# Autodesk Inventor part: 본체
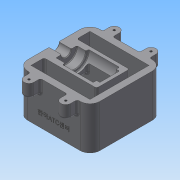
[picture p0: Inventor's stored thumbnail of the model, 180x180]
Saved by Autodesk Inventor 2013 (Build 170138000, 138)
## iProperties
Created: 2018-01
Part Number: 본체
Material: 일반
Document SubType Name: Modeling
Designer: Administrator
Density: 1 g/cm^3
Mass: 367.227 g
Surface Area: 841.146 cm^2
Volume: 367.227 cm^3
Author: Administrator
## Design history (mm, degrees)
sketch "스케치1"
  geometry: L1 (-55, -55)-(55, -55); L2 (55, -55)-(55, 55); L3 (55, 55)-(-55, 55); L4 (-55, 55)-(-55, -55); L5 (-55, -55)-(55, 55); L6 (55, -55)-(-55, 55); 1 further point
  constraints: 12 end point, 2 midpoint, 2 parallel, 1 horizontal, 1 perpendicular
  dimensions: "d0" = 110 distance of L3.end L2.end; "d1" = 110 distance of L2.end L1.end
extrude "돌출1" new body sketch "스케치1" distance "d2" = 65; taper "d3" = 0 deg
sketch "스케치2"
  geometry: L1 (55, 55)-(-55, 55) reference; L2 (-55, 55)-(-55, -55) reference; L3 (-55, -55)-(55, -55) reference; L4 (55, -55)-(55, 55) reference; L5 (55, 55)-(-55, 55) reference; L6 (-55, 55)-(-55, -55) reference; L7 (-55, 65)-(-1, 65); L8 (0, 55)-(0, 82.345); L9 (-35.5, 65)-(-35.5, 55); L10 (-20.5, 65)-(-20.5, 55); L11 (-35.5, 55)-(-20.5, 55); L12 (20.5, 65)-(20.5, 55); L13 (35.5, 55)-(20.5, 55); L14 (35.5, 65)-(35.5, 55); A1 r 7.5 centre (-28, 65) between (-20.5, 65) and (-35.5, 65); A2 r 7.5 centre (28, 65) between (35.5, 65) and (20.5, 65); 3 further points
  constraints: 16 end point, 5 symmetric about line, 4 midpoint, 4 point on circle, 4 point on line, 3 perpendicular, 2 centre point, 2 tangent, 1 coincident, 1 collinear, 1 horizontal alignment, 1 parallel, 1 other
  dimensions: "d5" = 7.5 radius of A1; "d6" = 27 distance from line of L2 A1.centre; "d7" = 10 distance from line of L1 A2.centre
extrude "돌출2" join sketch "스케치2" distance "d8" = 20; taper "d9" = 0 deg
sketch "스케치3"
  geometry: A1 r 7.5 centre (-28, -65) between (-35.5, -65) and (-20.5, -65) reference; A2 r 7.5 centre (28, -65) between (20.5, -65) and (35.5, -65) reference; A3 r 7.5 centre (28, 65) between (35.5, 65) and (20.5, 65) reference; A4 r 7.5 centre (-28, 65) between (-20.5, 65) and (-35.5, 65) reference; 5 further points
  constraints: 4 coincident
hole "구멍1" sketch "스케치3" at (-28, 65), (28, 65), (28, -65), (-28, -65) diameter "d10" = 3.242; stored, may be unused: countersink angle "d14" = 90 deg, drill point angle "d16" = 118 deg; dims "d11" = 9, "d12" = 4, "d13" = 2, "d15" = 11
sketch "스케치4"
  geometry: L1 (55, -55)-(55, 55) reference; L2 (20.5, 55)-(-20.5, 55) reference; L3 (-55, -55)-(-35.5, -55) reference; L4 (-35.5, -55)-(-35.5, -65) reference; L5 (-20.5, -65)-(-20.5, -55) reference; L6 (-20.5, -55)-(20.5, -55) reference; L7 (20.5, -65)-(20.5, -55) reference; L8 (35.5, -55)-(35.5, -65) reference; L9 (35.5, -55)-(55, -55) reference; L10 (55, -55)-(55, 55) reference; L11 (55, 55)-(35.5, 55) reference; L12 (35.5, 55)-(35.5, 65) reference; L13 (20.5, 65)-(20.5, 55) reference; L14 (20.5, 55)-(-20.5, 55) reference; L15 (-20.5, 65)-(-20.5, 55) reference; L16 (-35.5, 55)-(-35.5, 65) reference; L17 (-35.5, 55)-(-55, 55) reference; L18 (-55, 55)-(-55, -55) reference; L19 (-45, -45)-(45, -45); L20 (45, -45)-(45, 45); L21 (45, 45)-(-45, 45); L22 (-45, -45)-(45, 45); L23 (45, -45)-(-45, 45); L24 (-45, 25)-(35, 25); L25 (35, 25)-(35, -25); L26 (35, -25)-(-45, -25); L27 (-45, 45)-(-45, 25); L28 (-45, -25)-(-45, -45); C1 r 1.621 at (28, -65) reference; C2 r 1.621 at (-28, 65) reference; C3 r 1.621 at (28, 65) reference; C4 r 1.621 at (-28, -65) reference; A1 r 7.5 centre (-28, -65) between (-35.5, -65) and (-20.5, -65) reference; A2 r 7.5 centre (28, -65) between (20.5, -65) and (35.5, -65) reference; A3 r 7.5 centre (28, 65) between (35.5, 65) and (20.5, 65) reference; A4 r 7.5 centre (-28, 65) between (-20.5, 65) and (-35.5, 65) reference; 1 further point
  constraints: 20 end point, 4 parallel, 2 horizontal, 2 midpoint, 2 perpendicular
  dimensions: "d17" = 90 distance of L21.end L20.end; "d18" = 90 distance of L20.end L19.end; "d19" = 30 distance between parallel lines of L24 L2; "d20" = 20 distance between parallel lines of L25 L1; "d22" = 20 distance between parallel lines of L24 L21; "d28" = 30 distance between parallel lines of L6 L26
extrude "돌출3" cut sketch "스케치4" stored distance "d23" = 20; taper "d24" = 0 deg
sketch "스케치5"
  geometry: L1 (65, 110)-(65, 0) reference; C1 r 7.5 at (65, 55); 1 further point
  constraints: 1 centre point, 1 midpoint
  dimensions: "d25" = 15 diameter of C1
extrude "돌출4" cut sketch "스케치5" distance "d26" = 85; taper "d27" = 0 deg
node "작업 평면2"
  node "작업 평면1"
sketch "스케치6"
  geometry: C1 r 16 at (0, 65); A1 r 7.5 centre (0, 65) between (-7.5, 65) and (7.5, 65) reference; 1 further point
  constraints: 1 centre point, 1 coincident
  dimensions: "d31" = 32 diameter of C1
extrude "돌출5" cut sketch "스케치6" distance "d32" = 61; taper "d33" = 0 deg
node "작업 평면3"
sketch "스케치7"
  geometry: C1 r 20 at (0, 65); A1 r 16 centre (0, 65) between (-16, 65) and (16, 65) reference; 1 further point
  constraints: 1 centre point, 1 coincident
  dimensions: "d35" = 40 diameter of C1
extrude "돌출6" cut sketch "스케치7" distance "d36" = 47; taper "d37" = 0 deg
node "작업 평면4"
sketch "스케치8"
  geometry: C1 r 15 at (65, 0); A1 r 7.5 centre (65, 0) between (65, 7.5) and (65, -7.5) reference; 1 further point
  constraints: 1 centre point, 1 coincident
  dimensions: "d39" = 30 diameter of C1
extrude "돌출7" cut sketch "스케치8" distance "d40" = 5; taper "d41" = 0 deg
node "작업 평면5"
sketch "스케치14"
  geometry: L1 (-18.5, 15)-(18.5, 15); L2 (18.5, 15)-(18.5, -15); L3 (18.5, -15)-(-18.5, -15); L4 (-18.5, -15)-(-18.5, 15); 3 further points
  constraints: 8 end point, 2 midpoint, 2 parallel, 1 horizontal, 1 horizontal alignment, 1 perpendicular, 1 vertical alignment
  dimensions: "d64" = 37 distance of L1.start L1.end; "d66" = 30 distance of L1.end L2.end
extrude "돌출11" cut sketch "스케치14" distance "d67" = 35; taper "d68" = 0 deg
sketch "스케치15"
  geometry: L1 (45, 0)-(-35, 0) reference; L2 (-35, 65)-(-35, 0) reference; L3 (45, 65)-(45, 0) reference; L4 (-35, 30)-(45, 8.564); L5 (45, 8.564)-(45, 0); L6 (-35, 0)-(45, 0); L7 (-35, 30)-(-35, 0); 1 further point
  constraints: 8 end point, 2 perpendicular, 2 point on line, 1 collinear
  dimensions: "d69" = 30 distance from line of L1 L4.start; "d70" = 105 deg angle of L3 L4
extrude "돌출12" cut sketch "스케치15" stored distance "d71" = 55; taper "d72" = 0 deg
sketch "스케치16"
  geometry: L1 (-35, 30)-(45, 8.564) reference; L2 (55, 0)-(55, 65) reference; L3 (-15.681, 30)-(55, 11.061); L4 (18.5, 30)-(-18.5, 30) reference; L5 (18.5, 38.841)-(55, 29.061); L6 (18.5, 51.771)-(18.5, 30) reference; L7 (18.5, 38.841)-(-15.681, 30); L8 (55, 29.061)-(55, 11.061); 1 further point
  constraints: 8 end point, 4 point on line, 2 parallel, 1 collinear
  dimensions: "d73" = 5 distance between parallel lines of L1 L3; "d74" = 18 distance of L3.end L5.end
extrude "돌출13" cut sketch "스케치16" stored distance "d75" = 30; taper "d76" = 0 deg
chamfer "모따기1" distance "d77" = 1; stored, may be unused: second distance "d78" = 2, angle "d79" = 45 deg
fillet "모깎기1" dims "d80" = 15
fillet "모깎기2" dims "d81" = 3
fillet "모깎기3" dims "d82" = 3
fillet "모깎기4" dims "d83" = 3
fillet "모깎기5" dims "d84" = 3
fillet "모깎기6" dims "d85" = 3
sketch "스케치17"
  geometry: L1 (0, 0)-(80, 0) reference; L2 (-15, 65)-(-15, 0) reference; 2 further points
  constraints: 1 other
  dimensions: "d86" = 20 distance from line of point (40, 20) L1; "d87" = 55 distance from line of point (40, 20) L2
feature "엠보싱1" sketch "스케치17" dims "d0" = 110, "d1" = 110, "d5" = 7.5, "d6" = 27, "d7" = 10, "d88" = 0.5, "d89" = 0
node "솔리드1"
mirror "대칭1"
node "투영된 루프1"
node "투영된 루프2"
other parameters: "d29" = -55, "d30" = 19, "d34" = 14, "d38" = 65, "d63" = 65
